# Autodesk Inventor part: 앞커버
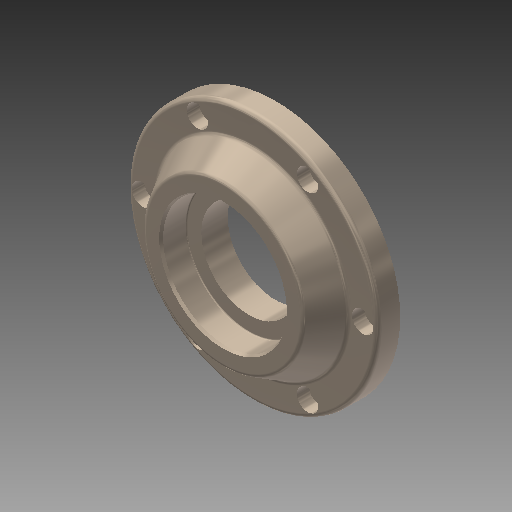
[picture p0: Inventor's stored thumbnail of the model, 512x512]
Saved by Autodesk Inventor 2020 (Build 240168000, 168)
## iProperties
Created: 2013-01
Part Number: 앞커버
Document SubType Name: Modeling
Designer: 한국산업디자인학원[gmhk.co.kr]
Density: 2.71 g/cm^3
Material: 알루미늄 6061
Mass: 415.969 g
Surface Area: 272.105 cm^2
Volume: 153.494 cm^3
Appearance: 알루미늄 - 평지(2)
Author: 한국산업디자인학원[gmhk.co.kr]
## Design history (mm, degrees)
sketch "스케치2"
  geometry: L1 (-55, 0)-(55, 0) reference; L2 (35.98, -6)-(-35.98, -6) reference; L3 (-42.5, -25)-(-42.5, 0) reference; L4 (-37, -6)-(-37, 0); L5 (-55, 0)-(-55, 10); L6 (-55, 10)-(-42.5, 10); L7 (-37, -6)-(-42.5, -6); L8 (-42.5, 10)-(-34.994, 23); L9 (-34.994, 23)-(0, 23); L10 (-55, 0)-(-42.5, 0); L11 (-42.5, -6)-(-42.5, 0); L12 (0, 0)-(0, 23); L13 (0, 0)-(-37, 0)
  constraints: 22 end point, 4 perpendicular, 3 collinear, 2 parallel, 2 point on line, 1 vertical, 2 other
  dimensions: "d2" = 10 distance of L1.start L5.end; "d4" = 120 deg angle of L8 L6; "d5" = 13 distance between parallel lines of L6 L9; "d6" = 74 diameter of L4 L12; "d7" = 85 diameter of L6.end L12
revolve "회전1" sketch "스케치2" stored, may be unused: angle "d8" = 90 deg
fillet "모깎기1" dims "d9" = 2
sketch "스케치3"
  geometry: C1 r 2.067 at (48.5, 0) reference; 1 further point
hole "구멍1" sketch "스케치3" at (48.5, 0) diameter "d10" = 5.5; stored, may be unused: countersink angle "d14" = 90 deg, drill point angle "d16" = 118 deg; dims "d11" = 6, "d12" = 9.5, "d13" = 5.4, "d15" = 8
fillet "모깎기2" dims "d20" = 3
chamfer "모따기1" distance "d21" = 1; stored, may be unused: second distance "d22" = 2, angle "d23" = 45 deg
sketch "스케치4"
  geometry: L1 (-33.84, 23)-(33.84, 23) reference; L2 (34, 0)-(-34, 0) reference; L3 (0, 0)-(0, 23); L4 (27.5, 21.9)-(27.5, 12.1); L5 (27, 11.6)-(21, 11.6); L6 (21, 11.6)-(21, 0); L7 (27.5, 21.9)-(28.135, 23); A1 r 0.5 centre (27, 12.1) between (27, 11.6) and (27.5, 12.1)
  constraints: 10 end point, 2 perpendicular, 2 point on circle, 2 point on line, 2 tangent, 1 centre point, 1 midpoint, 1 parallel
  dimensions: "d24" = 11.4 distance between parallel lines of L5 L1; "d25" = 1.1 distance from line of L4.start L1; "d26" = 30 deg angle of L7 L4; "d27" = 0.5 radius of A1; "d28" = 55 diameter of L4 L3; "d29" = 42 diameter of L6 L3
revolve "회전2" sketch "스케치4" stored, may be unused: angle "d30" = 90 deg
node "솔리드1"
pattern_circular "원형 패턴1" dims angle "d18" = 360 deg
node "참조1"
node "참조2"
node "참조3"
